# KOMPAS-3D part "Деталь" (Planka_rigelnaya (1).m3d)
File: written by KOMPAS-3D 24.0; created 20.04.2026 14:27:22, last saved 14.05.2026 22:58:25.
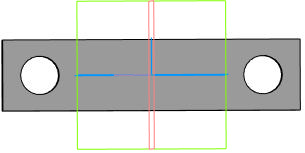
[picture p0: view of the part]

Document properties: Автор: TMK; Полное имя файла: E:\test_kompas\all_v22\Planka_rigelnaya (1).m3d; Организация: TMK

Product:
- Part/product: Деталь
    Масса: 0.134151

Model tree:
1. Эскиз:1
2. Элемент выдавливания:1
     Расстояние 2 = 8
3. Эскиз:2
4. Элемент выдавливания:2
     Расстояние 2 = 10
